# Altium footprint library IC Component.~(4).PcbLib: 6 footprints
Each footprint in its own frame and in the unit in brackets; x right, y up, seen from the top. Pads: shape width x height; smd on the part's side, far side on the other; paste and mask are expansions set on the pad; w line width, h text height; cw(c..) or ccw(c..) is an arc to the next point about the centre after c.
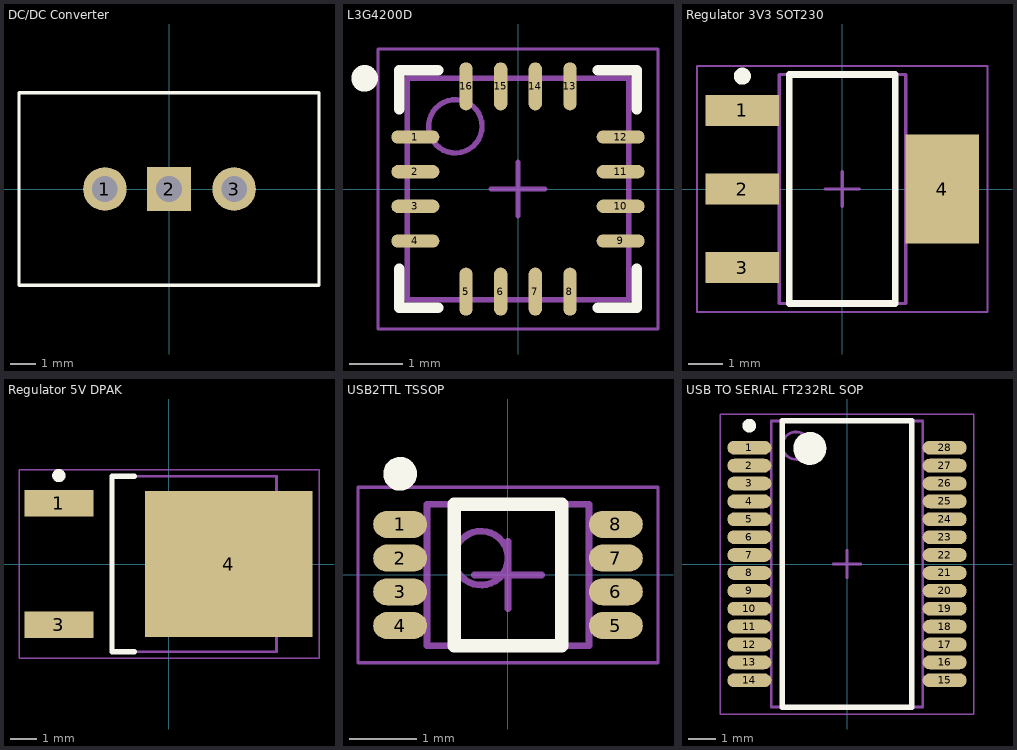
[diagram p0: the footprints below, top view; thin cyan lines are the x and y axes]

## DC/DC Converter [mm]
pads (3):
  round 1.7 hole 1: 1(-2.5,0) 3(2.54,0)
  rect 1.7x1.7 hole 1: 2(0,0)
Top Overlay:
  lines w0.127: -5.85,-3.75 -5.85,3.75 5.85,3.75 5.85,-3.75 -5.85,-3.75

## L3G4200D [mm] "QFN, 16-Leads, Body 4,00x4,00mm, Pitch 0,65mm, Thermal Pad 2,03x2,03mm, IPC Medium Density"
height 1.1
pads (16):
  oval 0.9x0.25 smd: 1(-1.925,0.975) 2(-1.925,0.325) 3(-1.925,-0.325) 4(-1.925,-0.975) 9(1.925,-0.975) 10(1.925,-0.325) 11(1.925,0.325) 12(1.925,0.975)
  oval 0.25x0.9 smd: 5(-0.975,-1.925) 6(-0.325,-1.925) 7(0.325,-1.925) 8(0.975,-1.925) 13(0.975,1.925) 14(0.325,1.925) 15(-0.325,1.925) 16(-0.975,1.925)
Top Overlay:
  circle w0.25: c-2.875,2.075 r0.125
  lines w0.2: -2.225,-1.5 -2.225,-2.225 -1.5,-2.225 ; -2.225,1.5 -2.225,2.225 -1.5,2.225 ; 1.5,-2.225 2.225,-2.225 2.225,-1.5 ; 1.5,2.225 2.225,2.225 2.225,1.5
Mechanical 13:
  circle w0.1: c-1.175,1.175 r0.5
  lines w0.1: -2.075,-2.075 2.075,-2.075 2.075,2.075 -2.075,2.075 -2.075,-2.075
Mechanical 15:
  lines w0.05: -2.625,-2.625 2.625,-2.625 2.625,2.625 -2.625,2.625 -2.625,-2.625
  lines w0.1: -0.5,0 0.5,0 ; 0,-0.5 0,0.5
3D body: height 1.1, standoff 0.2, extent -2.075,-2.075 2.075,2.075

## Regulator 3V3 SOT230 [mm] "SOT223, 4-Leads, Body 6,50x7,00mm (avg), Pitch 2,30mm, IPC Medium Density"
height 1.8
pads (4):
  rect 2.15x0.9 smd: 1(-2.925,2.3) 2(-2.925,0) 3(-2.925,-2.3)
  rect 2.15x3.2 smd: 4(2.925,0)
Top Overlay:
  circle w0.25: c-2.925,3.3 r0.125
  lines w0.2: -1.55,-3.35 1.55,-3.35 1.55,3.35 -1.55,3.35 -1.55,-3.35
Mechanical 13:
  lines w0.1: -1.85,-3.35 1.85,-3.35 1.85,3.35 -1.85,3.35 -1.85,-3.35
Mechanical 15:
  lines w0.05: -4.25,-3.6 4.25,-3.6 4.25,3.6 -4.25,3.6 -4.25,-3.6
  lines w0.1: -0.5,0 0.5,0 ; 0,-0.5 0,0.5
3D body: height 1.8, standoff 0.02, extent -1.85,-3.35 1.85,3.35

## Regulator 5V DPAK [mm] "D-PAK, 3-Pads, Body 6,20x6,66mm (max), IPC Medium Density"
height 2.4
pads (3):
  rect 2.6x1 smd: 1(-4.15,2.28) 3(-4.15,-2.28)
  rect 6.3x5.5 smd: 4(2.25,0)
Top Overlay:
  circle w0.25: c-4.15,3.33 r0.125
  lines w0.2: -1.3,-3.3 -2.15,-3.3 -2.15,3.3 -1.3,3.3
Mechanical 13:
  lines w0.1: -2.15,-3.3 -2.15,3.3 4.05,3.3 4.05,-3.3 -2.15,-3.3
Mechanical 15:
  lines w0.05: -5.65,-3.55 -5.65,3.55 5.65,3.55 5.65,-3.55 -5.65,-3.55
  lines w0.1: -0.5,0 0.5,0 ; 0,-0.5 0,0.5
3D body: height 2.4, standoff 0, extent -2.15,-3.3 4.05,3.3

## USB2TTL TSSOP [mm] "TSSOP, 8-Leads, Body 2,05x2,35mm, Pitch 0,50mm, IPC Medium Density"
height 0.9
pads (8):
  oval 0.8x0.4 smd: 1(-1.6,0.75) 2(-1.6,0.25) 3(-1.6,-0.25) 4(-1.6,-0.75) 5(1.6,-0.75) 6(1.6,-0.25) 7(1.6,0.25) 8(1.6,0.75)
Top Overlay:
  circle w0.25: c-1.6,1.5 r0.125
  lines w0.2: -0.8,-1.05 0.8,-1.05 0.8,1.05 -0.8,1.05 -0.8,-1.05
Mechanical 13:
  circle w0.1: c-0.4,0.25 r0.4
  lines w0.1: -1.2,-1.05 1.2,-1.05 1.2,1.05 -1.2,1.05 -1.2,-1.05
Mechanical 15:
  lines w0.05: -2.225,-1.3 2.225,-1.3 2.225,1.3 -2.225,1.3 -2.225,-1.3
  lines w0.1: -0.5,0 0.5,0 ; 0,-0.5 0,0.5
3D body: height 0.9, standoff 0.1, extent -1.2,-1.05 1.2,1.05

## USB TO SERIAL FT232RL SOP [mm] "SOP, 28-Leads, Body 10,25x5,40mm, Pitch 0,65mm, IPC Medium Density"
height 2
pads (28):
  oval 1.6x0.5 smd: 1(-3.55,4.225) 2(-3.55,3.575) 3(-3.55,2.925) 4(-3.55,2.275) 5(-3.55,1.625) 6(-3.55,0.975) 7(-3.55,0.325) 8(-3.55,-0.325) 9(-3.55,-0.975) 10(-3.55,-1.625) 11(-3.55,-2.275) 12(-3.55,-2.925) 13(-3.55,-3.575) 14(-3.55,-4.225) 15(3.55,-4.225) 16(3.55,-3.575) 17(3.55,-2.925) 18(3.55,-2.275) 19(3.55,-1.625) 20(3.55,-0.975) 21(3.55,-0.325) 22(3.55,0.325) 23(3.55,0.975) 24(3.55,1.625) 25(3.55,2.275) 26(3.55,2.925) 27(3.55,3.575) 28(3.55,4.225)
Top Overlay:
  circle w0.25: c-3.55,5.025 r0.125
  circle w0.6: c-1.35,4.2 r0.3
  lines w0.2: -2.35,-5.2 -2.35,5.2 2.35,5.2 2.35,-5.2 -2.35,-5.2
Mechanical 13:
  circle w0.1: c-1.85,4.3 r0.5
  lines w0.1: -2.75,-5.2 -2.75,5.2 2.75,5.2 2.75,-5.2 -2.75,-5.2
Mechanical 15:
  lines w0.05: -4.6,-5.45 -4.6,5.45 4.6,5.45 4.6,-5.45 -4.6,-5.45
  lines w0.1: -0.5,0 0.5,0 ; 0,-0.5 0,0.5
3D body: height 2, standoff 0.05, extent -2.75,-5.2 2.75,5.2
